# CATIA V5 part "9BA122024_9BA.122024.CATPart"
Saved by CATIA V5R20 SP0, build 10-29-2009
Part number: 9BA122024_9BA.122024
Revision: ANY
Definition: UNKNOWN
Nomenclature: 9BA122024_9BA.122024
Source: Unknown
Bounding box of the stored display mesh (mm): x -11.818 to 11.818, y 0 to 25.5, z -12 to 12
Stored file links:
  C:\Users\Utente\Desktop\IO LAVORO\3D X SITO CF\CUMSA\3D files BA\BA 122024\9BA122024_9BA.122024.CATPart
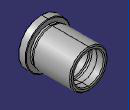
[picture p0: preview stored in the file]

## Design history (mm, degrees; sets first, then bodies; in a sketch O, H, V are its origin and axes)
Body1 "Cortar-Extruir1" (main body)
  Solid1: solid without history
